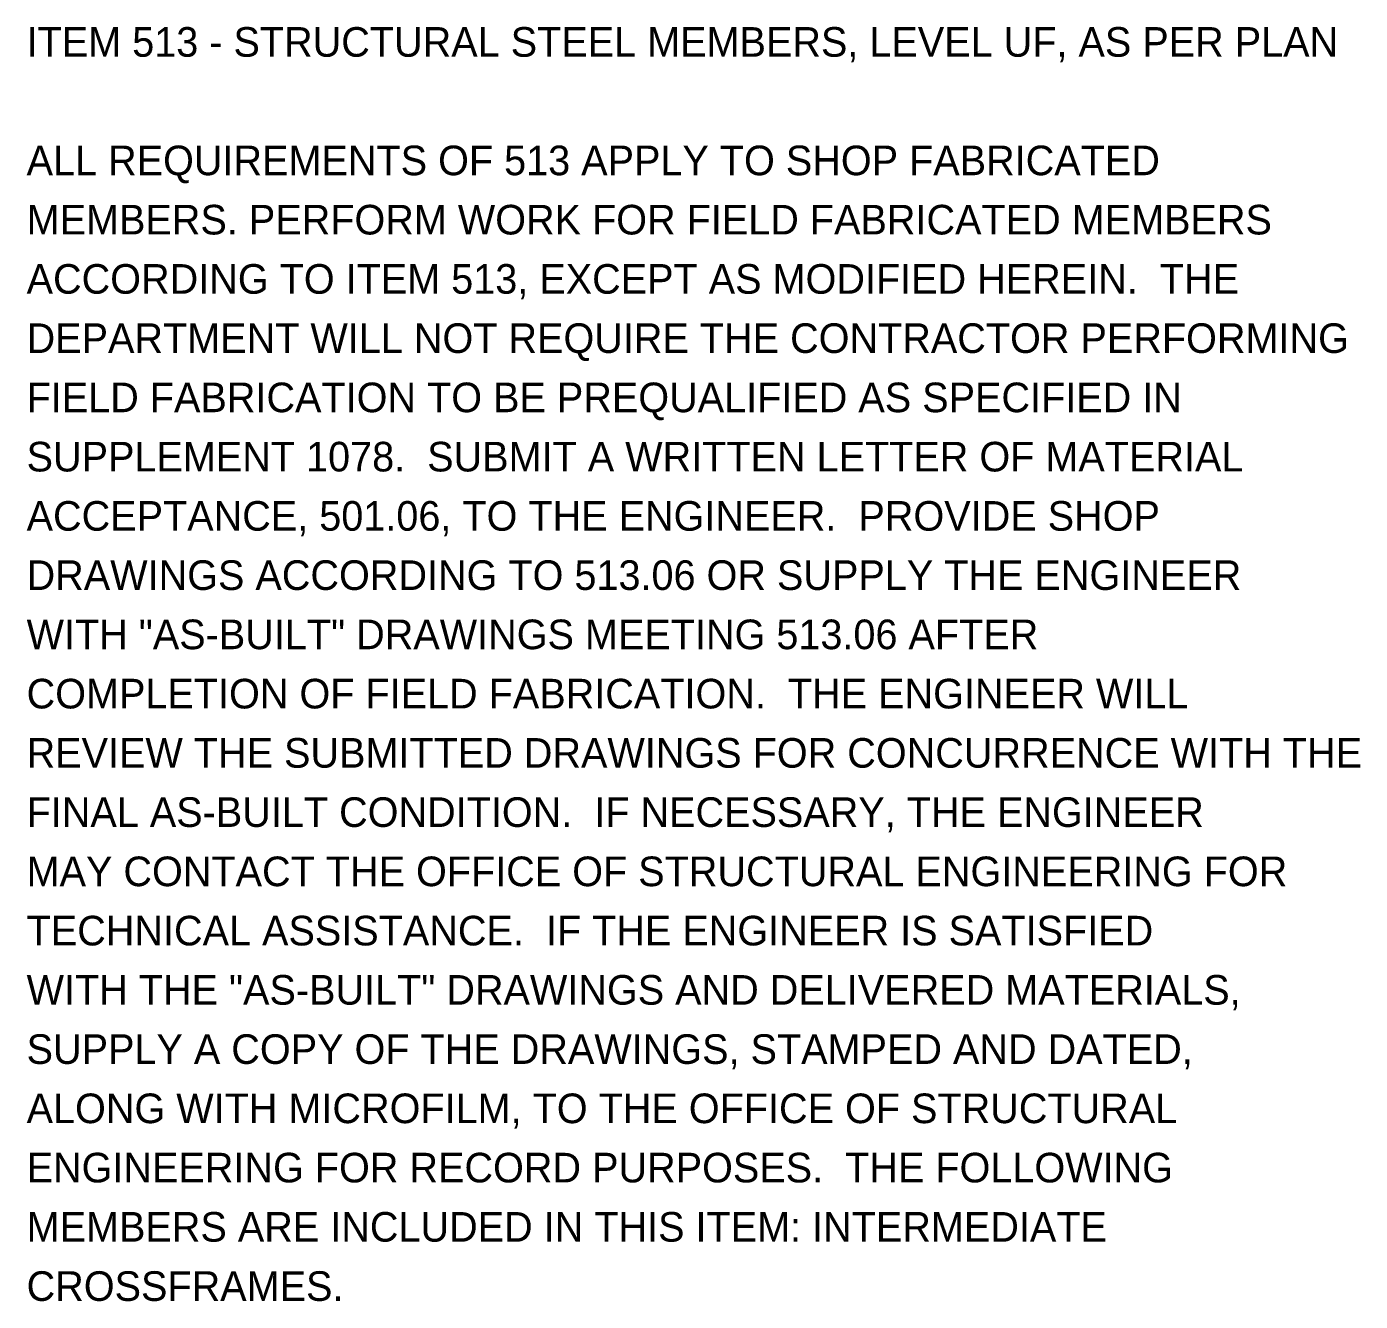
# Model space of a CAD drawing. Extents: x -51.6 to 45.5, y -38.3 to 35.3.
# Drawn here: x -29.32 to -23.02, y 29.28 to 35.3 of the extents above; entities that cross this region are included whole.
import ezdxf

# ---------------------------------------------------------------- set-up
doc = ezdxf.new("R2010")
doc.units = 0
doc.layers.add('BD_P_Text', color=7, linetype='Continuous')

msp = doc.modelspace()

# ---------------------------------------------------------------- texts
at = {"layer": 'BD_P_Text'}
for s, p in [('ITEM 513 - STRUCTURAL STEEL MEMBERS, LEVEL UF, AS PER PLAN', (-29.3226, 35.1573)), ('ALL REQUIREMENTS OF 513 APPLY TO SHOP FABRICATED ', (-29.3226, 34.5973)), ('MEMBERS. PERFORM WORK FOR FIELD FABRICATED MEMBERS ', (-29.3226, 34.3173)), ('ACCORDING TO ITEM 513, EXCEPT AS MODIFIED HEREIN.  THE ', (-29.3226, 34.0373)), ('DEPARTMENT WILL NOT REQUIRE THE CONTRACTOR PERFORMING ', (-29.3226, 33.7573)), ('FIELD FABRICATION TO BE PREQUALIFIED AS SPECIFIED IN ', (-29.3226, 33.4773)), ('SUPPLEMENT 1078.  SUBMIT A WRITTEN LETTER OF MATERIAL ', (-29.3226, 33.1973)), ('ACCEPTANCE, 501.06, TO THE ENGINEER.  PROVIDE SHOP ', (-29.3226, 32.9173)), ('DRAWINGS ACCORDING TO 513.06 OR SUPPLY THE ENGINEER ', (-29.3226, 32.6373)), ('WITH "AS-BUILT" DRAWINGS MEETING 513.06 AFTER ', (-29.3226, 32.3573)), ('COMPLETION OF FIELD FABRICATION.  THE ENGINEER WILL ', (-29.3226, 32.0773)), ('REVIEW THE SUBMITTED DRAWINGS FOR CONCURRENCE WITH THE ', (-29.3226, 31.7973)), ('FINAL AS-BUILT CONDITION.  IF NECESSARY, THE ENGINEER ', (-29.3226, 31.5173)), ('MAY CONTACT THE OFFICE OF STRUCTURAL ENGINEERING FOR ', (-29.3226, 31.2373)), ('TECHNICAL ASSISTANCE.  IF THE ENGINEER IS SATISFIED ', (-29.3226, 30.9573)), ('WITH THE "AS-BUILT" DRAWINGS AND DELIVERED MATERIALS, ', (-29.3226, 30.6773)), ('SUPPLY A COPY OF THE DRAWINGS, STAMPED AND DATED, ', (-29.3226, 30.3973)), ('ALONG WITH MICROFILM, TO THE OFFICE OF STRUCTURAL ', (-29.3226, 30.1173)), ('ENGINEERING FOR RECORD PURPOSES.  THE FOLLOWING ', (-29.3226, 29.8373)), ('MEMBERS ARE INCLUDED IN THIS ITEM: INTERMEDIATE ', (-29.3226, 29.5573)), ('CROSSFRAMES.', (-29.3226, 29.2773))]:
    msp.add_text(s, height=0.14, dxfattribs=at).set_placement(p)

doc.saveas('drawing.dxf')
